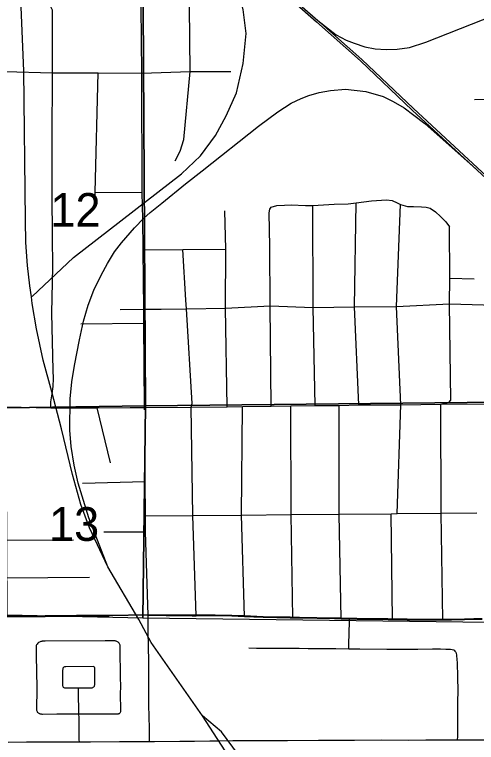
# Model space of a CAD drawing. Extents: x 0 to 40.2, y 0 to 22.
# Drawn here: x 2.971 to 3.545, y 17.261 to 18.165 of the extents above; entities that cross this region are included whole.
import ezdxf

# ---------------------------------------------------------------- set-up
doc = ezdxf.new("R2010")
doc.units = 0
for name, color, linetype in [('GM_X_City_Street', 7, 'Continuous'), ('GM_X_Corporation', 7, 'Continuous'), ('GM_X_Major_Lake_Text', 7, 'Continuous'), ('GM_X_Major_River', 7, 'Continuous'), ('GM_X_Unincorporated_Location', 7, 'Continuous')]:
    doc.layers.add(name, color=color, linetype=linetype)

msp = doc.modelspace()

# ---------------------------------------------------------------- linework, layer by layer
at = {"layer": 'GM_X_Corporation'}
for points in [[(4.11898, 18.68419), (4.13231, 17.68919), (3.13419, 17.6788), (3.1284, 18.66934)], [(3.1284, 18.66934), (3.13419, 17.6788), (2.96095, 17.67632), (2.96072, 17.91012), (2.96123, 18.66685)], [(4.13231, 17.68919), (4.13209, 17.4086), (3.75982, 17.40742), (3.1308, 17.4152), (3.13419, 17.6788)], [(2.96095, 17.67632), (3.13419, 17.6788), (3.1308, 17.4152), (2.96215, 17.41928)]]:
    msp.add_lwpolyline(points, close=True, dxfattribs=at)
for points in [[(2.9617, 17.41769), (2.99033, 17.41796), (3.00943, 17.4181), (3.03209, 17.41845), (3.04821, 17.41854), (3.08872, 17.4187), (3.13707, 17.41967), (3.1596, 17.41929), (3.19192, 17.41893), (3.19659, 17.41895), (3.22053, 17.41908), (3.24107, 17.41867), (3.25657, 17.41809), (3.27994, 17.41721), (3.31354, 17.41646), (3.31679, 17.41639), (3.32524, 17.41618), (3.36862, 17.41544), (3.37667, 17.41527), (3.38417, 17.41511), (3.38703, 17.41504), (3.39658, 17.41478), (3.41211, 17.41473), (3.43513, 17.41443), (3.44068, 17.41434), (3.45874, 17.41404), (3.49872, 17.41383), (3.50305, 17.41386), (3.51367, 17.41392), (3.52995, 17.41417), (3.5416, 17.41451), (3.55201, 17.41452)], [(3.55201, 17.41452), (3.5416, 17.41451), (3.52995, 17.41417), (3.51367, 17.41392), (3.50305, 17.41386), (3.49872, 17.41383), (3.45874, 17.41404), (3.44068, 17.41434), (3.43513, 17.41443), (3.41211, 17.41473), (3.39658, 17.41478), (3.38703, 17.41504), (3.38417, 17.41511), (3.37667, 17.41527), (3.36862, 17.41544), (3.32524, 17.41618), (3.31679, 17.41639), (3.31354, 17.41646), (3.27994, 17.41721), (3.25657, 17.41809), (3.24107, 17.41867), (3.22053, 17.41908), (3.19659, 17.41895), (3.19192, 17.41893), (3.1596, 17.41929), (3.13707, 17.41967), (3.08872, 17.4187), (3.04821, 17.41854), (3.03209, 17.41845), (3.00943, 17.4181), (2.99033, 17.41796), (2.9617, 17.41769)], [(3.55201, 17.41452), (3.5416, 17.41451), (3.52995, 17.41417), (3.51367, 17.41392), (3.50305, 17.41386), (3.49872, 17.41383), (3.45874, 17.41404), (3.44068, 17.41434), (3.43513, 17.41443), (3.41211, 17.41473), (3.39658, 17.41478), (3.38703, 17.41504), (3.38417, 17.41511), (3.37667, 17.41527), (3.36862, 17.41544), (3.32524, 17.41618), (3.31679, 17.41639), (3.31354, 17.41646), (3.27994, 17.41721), (3.25657, 17.41809), (3.24107, 17.41867), (3.22053, 17.41908), (3.19659, 17.41895), (3.19192, 17.41893), (3.1596, 17.41929), (3.13707, 17.41967), (3.08872, 17.4187), (3.04821, 17.41854), (3.03209, 17.41845), (3.00943, 17.4181), (2.99033, 17.41796), (2.9617, 17.41769)], [(2.9617, 17.41769), (2.99033, 17.41796), (3.00943, 17.4181), (3.03209, 17.41845), (3.04821, 17.41854), (3.08872, 17.4187), (3.13707, 17.41967), (3.1596, 17.41929), (3.19192, 17.41893), (3.19659, 17.41895), (3.22053, 17.41908), (3.24107, 17.41867), (3.25657, 17.41809), (3.27994, 17.41721), (3.31354, 17.41646), (3.31679, 17.41639), (3.32524, 17.41618), (3.36862, 17.41544), (3.37667, 17.41527), (3.38417, 17.41511), (3.38703, 17.41504), (3.39658, 17.41478), (3.41211, 17.41473), (3.43513, 17.41443), (3.44068, 17.41434), (3.45874, 17.41404), (3.49872, 17.41383), (3.50305, 17.41386), (3.51367, 17.41392), (3.52995, 17.41417), (3.5416, 17.41451), (3.55201, 17.41452)], [(3.55201, 17.41452), (3.5416, 17.41451), (3.52995, 17.41417), (3.51367, 17.41392), (3.50305, 17.41386), (3.49872, 17.41383), (3.45874, 17.41404), (3.44068, 17.41434), (3.43513, 17.41443), (3.41211, 17.41473), (3.39658, 17.41478), (3.38703, 17.41504), (3.38417, 17.41511), (3.37667, 17.41527), (3.36862, 17.41544), (3.32524, 17.41618), (3.31679, 17.41639), (3.31354, 17.41646), (3.27994, 17.41721), (3.25657, 17.41809), (3.24107, 17.41867), (3.22053, 17.41908), (3.19659, 17.41895), (3.19192, 17.41893), (3.1596, 17.41929), (3.13707, 17.41967), (3.08872, 17.4187), (3.04821, 17.41854), (3.03209, 17.41845), (3.00943, 17.4181), (2.99033, 17.41796), (2.9617, 17.41769)], [(2.9617, 17.41769), (2.99033, 17.41796), (3.00943, 17.4181), (3.03209, 17.41845), (3.04821, 17.41854), (3.08872, 17.4187), (3.13707, 17.41967), (3.1596, 17.41929), (3.19192, 17.41893), (3.19659, 17.41895), (3.22053, 17.41908), (3.24107, 17.41867), (3.25657, 17.41809), (3.27994, 17.41721), (3.31354, 17.41646), (3.31679, 17.41639), (3.32524, 17.41618), (3.36862, 17.41544), (3.37667, 17.41527), (3.38417, 17.41511), (3.38703, 17.41504), (3.39658, 17.41478), (3.41211, 17.41473), (3.43513, 17.41443), (3.44068, 17.41434), (3.45874, 17.41404), (3.49872, 17.41383), (3.50305, 17.41386), (3.51367, 17.41392), (3.52995, 17.41417), (3.5416, 17.41451), (3.55201, 17.41452)]]:
    msp.add_lwpolyline(points, dxfattribs=at)
at = {"layer": 'GM_X_Major_Lake_Text'}
for points in [[(2.93726, 17.69353), (2.93877, 17.6924), (2.96139, 17.67783), (3.0163, 17.67668), (3.06737, 17.67662)], [(3.11488, 17.67671), (3.13289, 17.67675), (3.13423, 17.67676), (3.19078, 17.67743), (3.23544, 17.6778), (3.25468, 17.67824), (3.29027, 17.67869), (3.31457, 17.67895), (3.34467, 17.67951), (3.37432, 17.67943), (3.39891, 17.68003), (3.45093, 17.6804), (3.50079, 17.68099), (3.55771, 17.68159), (3.57339, 17.68181), (3.63343, 17.68293)], [(3.06737, 17.67662), (3.07411, 17.67661), (3.11488, 17.67671)]]:
    msp.add_lwpolyline(points, dxfattribs=at)
at = {"layer": 'GM_X_Major_River'}
for points in [[(3.17893, 17.96677), (3.20214, 17.98942), (3.22086, 18.01438), (3.23408, 18.03898), (3.24692, 18.06733), (3.25513, 18.1039), (3.25885, 18.14122), (3.25513, 18.17108), (3.24543, 18.21063), (3.23335, 18.23466), (3.21707, 18.25616), (3.16603, 18.30644)], [(3.30443, 18.1928), (3.34645, 18.1555)], [(3.30596, 18.19455), (3.348, 18.15723)], [(3.348, 18.15723), (3.37096, 18.13968), (3.38311, 18.13303), (3.39324, 18.12898), (3.40623, 18.12466), (3.41916, 18.12213), (3.43274, 18.12138), (3.4465, 18.12166), (3.46177, 18.12382), (3.48191, 18.13019), (3.55262, 18.15791), (3.62812, 18.18751)], [(3.12587, 17.41372), (3.08729, 17.47893), (3.06471, 17.52756), (3.05386, 17.55651), (3.04358, 17.5937), (3.02969, 17.6503), (3.01767, 17.69647), (3.00711, 17.73555), (2.99857, 17.77463), (2.9935, 17.80604), (2.99234, 17.81429), (2.9905, 17.82787), (2.98769, 17.8533), (2.98529, 17.88154), (2.9849, 17.90952), (2.98289, 18.09501), (2.97948, 18.17371)], [(3.34645, 18.1555), (3.40098, 18.10707), (3.46511, 18.04617), (3.57841, 17.94139), (3.82062, 17.71495), (4.1455, 17.41498)], [(3.348, 18.15723), (3.40256, 18.10878), (3.46671, 18.04785), (3.58, 17.94309), (3.8222, 17.71665), (4.14708, 17.41668)], [(3.08729, 17.47893), (3.06356, 17.54001), (3.05024, 17.58314), (3.04561, 17.60543), (3.04185, 17.62844), (3.03996, 17.64885), (3.0404, 17.68778), (3.04242, 17.70863), (3.0459, 17.72904), (3.05212, 17.76088), (3.05704, 17.78404), (3.06269, 17.80387), (3.06992, 17.82254), (3.0789, 17.84121), (3.087, 17.85568), (3.0954, 17.87001), (3.10423, 17.88145), (3.12058, 17.90012), (3.13202, 17.91199), (3.13983, 17.91893), (3.15416, 17.93066), (3.18383, 17.95434), (3.20459, 17.97082), (3.27418, 18.02607), (3.29833, 18.04391), (3.31483, 18.05447), (3.32729, 18.06056), (3.33667, 18.06431), (3.34984, 18.06807), (3.36373, 18.07053), (3.38223, 18.07185), (3.40756, 18.06908), (3.42897, 18.06301), (3.44171, 18.05679), (3.45516, 18.04883), (3.46717, 18.03971), (3.48077, 18.02959), (3.54471, 17.97255)], [(2.99348, 17.81465), (3.0448, 17.86313), (3.17893, 17.96677)], [(3.42749, 16.31236), (3.42143, 16.37549), (3.41839, 16.40637), (3.36203, 16.74823), (3.34427, 16.83879), (3.33799, 16.8832), (3.32359, 16.97894), (3.3149, 17.0308), (3.29684, 17.09734), (3.28734, 17.13347), (3.26263, 17.1924), (3.24648, 17.22948), (3.20467, 17.29412), (3.141, 17.38537), (3.12587, 17.41372)], [(4.03805, 16.15637), (3.69141, 16.63399), (3.24242, 17.25514), (3.22847, 17.27443), (3.20468, 17.29411), (3.20467, 17.29412)]]:
    msp.add_lwpolyline(points, dxfattribs=at)
at = {"layer": 'GM_X_Unincorporated_Location'}
for p, q in [((3.07153, 17.9444), (3.12994, 17.94375)), ((3.51193, 17.83734), (3.54196, 17.83652)), ((3.05394, 17.7808), (3.13206, 17.78143)), ((3.09065, 17.6084), (3.07411, 17.67661)), ((3.056, 17.58297), (3.13363, 17.58521)), ((3.44091, 17.41378), (3.43914, 17.54509)), ((3.08249, 17.52239), (3.13413, 17.52261))]:
    msp.add_line(p, q, dxfattribs=at)
for points in [[(3.0163, 17.67668), (3.0163, 17.68397), (3.01823, 17.694), (3.01935, 17.70277), (3.01972, 17.7128), (3.01952, 17.72337), (3.01779, 17.79387), (3.01898, 17.8516), (3.01846, 17.88868), (3.01823, 17.94129), (3.01831, 18.00772), (3.01844, 18.09243), (3.01875, 18.16994), (3.01645, 18.17417), (3.01593, 18.31105), (3.0172, 18.31238), (3.01677, 18.34166)], [(3.12934, 18.0902), (3.12933, 18.09209), (3.1287, 18.17477)], [(3.17097, 17.98292), (3.17727, 17.99497), (3.18172, 18.00971), (3.18971, 18.0938), (3.18866, 18.17481)], [(2.88565, 18.09458), (2.93786, 18.09431), (2.95954, 18.09404), (3.01844, 18.09243), (3.0752, 18.09243), (3.12933, 18.09209), (3.18971, 18.0938), (3.23282, 18.0938), (3.23997, 18.0938)], [(3.07157, 17.92655), (3.07153, 17.9444), (3.0752, 18.09243)], [(3.13729, 17.41912), (3.13413, 17.52261), (3.13397, 17.54235), (3.13363, 17.58521), (3.13423, 17.67676), (3.13291, 17.67416), (3.13289, 17.67675), (3.13206, 17.78143), (3.13191, 17.79887), (3.13132, 17.87277), (3.13058, 17.91067), (3.12994, 17.94375), (3.12934, 18.0902)], [(3.54263, 18.05902), (3.62867, 18.06068), (3.75346, 18.06164), (3.79723, 18.0611), (3.83901, 18.05996), (3.87868, 18.05848), (4.00662, 18.06016), (4.06623, 18.06085), (4.12108, 18.06125)], [(3.28994, 17.92565), (3.29711, 17.92751), (3.30681, 17.92807), (3.31476, 17.92833), (3.33274, 17.92755), (3.34177, 17.92747), (3.36811, 17.92922), (3.3858, 17.92985), (3.39572, 17.93085), (3.41478, 17.93334), (3.43321, 17.93464), (3.44049, 17.93368), (3.44658, 17.93111), (3.45059, 17.929), (3.45947, 17.92643), (3.46698, 17.92636), (3.47687, 17.9261), (3.48236, 17.92561), (3.48734, 17.92413), (3.49425, 17.91967), (3.50049, 17.91387), (3.50696, 17.90733), (3.51164, 17.90132)], [(3.34467, 17.67951), (3.34202, 17.80123), (3.34177, 17.92747)], [(3.39891, 17.68003), (3.39339, 17.80181), (3.39572, 17.93085)], [(3.44631, 17.54516), (3.45093, 17.6804), (3.44551, 17.8024), (3.45059, 17.929)], [(3.23544, 17.6778), (3.23334, 17.80001), (3.23376, 17.87354), (3.23235, 17.92097)], [(3.29027, 17.67869), (3.2889, 17.8029), (3.28845, 17.87683), (3.28764, 17.91855), (3.28823, 17.92327), (3.28994, 17.92565)], [(3.50328, 17.4133), (3.50108, 17.54565), (3.50079, 17.68099), (3.51052, 17.68293), (3.51327, 17.6859), (3.51134, 17.80538), (3.51193, 17.83734), (3.51164, 17.90132)], [(3.13132, 17.87277), (3.18052, 17.87314), (3.23376, 17.87354)], [(3.19681, 17.4184), (3.19284, 17.54288), (3.19078, 17.67743), (3.19192, 17.68207), (3.18495, 17.79947), (3.18433, 17.80996), (3.18052, 17.87314)], [(3.1024, 17.79854), (3.13191, 17.79887), (3.15357, 17.79912), (3.18495, 17.79947), (3.23334, 17.80001), (3.2889, 17.8029), (3.34202, 17.80123), (3.39339, 17.80181), (3.44551, 17.8024), (3.51134, 17.80538), (3.56769, 17.80377), (3.57315, 17.80383), (3.63208, 17.80603)], [(3.2568, 17.41753), (3.25317, 17.54343), (3.25468, 17.67824)], [(3.31702, 17.41583), (3.31489, 17.54398), (3.31457, 17.67895)], [(3.37689, 17.41472), (3.3747, 17.54452), (3.3747, 17.54558), (3.37432, 17.67943)], [(3.13397, 17.54235), (3.19284, 17.54288), (3.25317, 17.54343), (3.31489, 17.54398), (3.3747, 17.54452), (3.43914, 17.54509), (3.44631, 17.54516), (3.50108, 17.54565), (3.54563, 17.54605)], [(2.78714, 17.51159), (2.96097, 17.51238), (3.04468, 17.51276)], [(2.79062, 17.4645), (2.95696, 17.46548), (2.96094, 17.46551), (3.0646, 17.46612)], [(2.96193, 17.41713), (2.99056, 17.4174), (3.00965, 17.41754), (3.03231, 17.41789), (3.04843, 17.41798), (3.08895, 17.41814)], [(3.13729, 17.41912), (3.15983, 17.41874), (3.19214, 17.41837), (3.19681, 17.4184), (3.22076, 17.41853), (3.2413, 17.41812), (3.2568, 17.41753), (3.28017, 17.41665), (3.31377, 17.4159), (3.31702, 17.41583), (3.32546, 17.41562), (3.36885, 17.41489), (3.37689, 17.41472), (3.38439, 17.41456), (3.38726, 17.41448), (3.39681, 17.41423), (3.41234, 17.41417), (3.43535, 17.41387), (3.44091, 17.41378), (3.45896, 17.41348), (3.49895, 17.41328), (3.50328, 17.4133), (3.5139, 17.41336), (3.53018, 17.41362), (3.54182, 17.41395), (3.55223, 17.41396)], [(3.13914, 17.26244), (3.1391, 17.26556), (3.13893, 17.27917), (3.13854, 17.29249), (3.13834, 17.30803), (3.13809, 17.33607), (3.13808, 17.35455), (3.13803, 17.36142), (3.13742, 17.39926), (3.13744, 17.41308), (3.13729, 17.41912)], [(3.38646, 17.37753), (3.38658, 17.38312), (3.38718, 17.41075), (3.38726, 17.41448)], [(3.05145, 17.29651), (3.06349, 17.2966), (3.0665, 17.29663), (3.07503, 17.2965), (3.08671, 17.29647), (3.09471, 17.29657), (3.09955, 17.29674), (3.10039, 17.29681), (3.10104, 17.29698), (3.10165, 17.29723), (3.10224, 17.29761), (3.10274, 17.29813), (3.1031, 17.29871), (3.10329, 17.29938), (3.10335, 17.30006), (3.10342, 17.30106), (3.10342, 17.30279), (3.10321, 17.32041), (3.10329, 17.33172), (3.10316, 17.34093), (3.10273, 17.37902), (3.10268, 17.38037), (3.10263, 17.38116), (3.10257, 17.38179), (3.10235, 17.38272), (3.10194, 17.38351), (3.10136, 17.38421), (3.10076, 17.3849), (3.10005, 17.38545), (3.09933, 17.38595), (3.09843, 17.38641), (3.09782, 17.38667), (3.09716, 17.38689), (3.09646, 17.38711), (3.09558, 17.38727), (3.09459, 17.38733), (3.0928, 17.38732), (3.08414, 17.38717), (3.00944, 17.38671), (3.00689, 17.38674), (3.00588, 17.38666), (3.00526, 17.3866), (3.00422, 17.38641), (3.00333, 17.38615), (3.0024, 17.3858), (3.00134, 17.38513), (3.00072, 17.38469), (3.00019, 17.38422), (2.99935, 17.38331), (2.99877, 17.38235), (2.99844, 17.38136), (2.99832, 17.38068), (2.99829, 17.37983), (2.99827, 17.37763), (2.99821, 17.37426), (2.99829, 17.36297), (2.99863, 17.3549), (2.9988, 17.34866), (2.9989, 17.34187), (2.99895, 17.33623), (2.99893, 17.32696), (2.99878, 17.30318), (2.9988, 17.30252), (2.9989, 17.3014), (2.99904, 17.3005), (2.99934, 17.29952), (2.99971, 17.29886), (3.00023, 17.29825), (3.00085, 17.29778), (3.00148, 17.2974), (3.00231, 17.29704), (3.00297, 17.29683), (3.00367, 17.29666), (3.00439, 17.29652), (3.00514, 17.29643), (3.00601, 17.29634), (3.02382, 17.29649), (3.04725, 17.29651), (3.05145, 17.29651)], [(3.26216, 17.37847), (3.27196, 17.37817), (3.28458, 17.37828), (3.31436, 17.37819), (3.32466, 17.37799), (3.33587, 17.3778), (3.37036, 17.37768), (3.38646, 17.37753)], [(3.38646, 17.37753), (3.40018, 17.3774), (3.43375, 17.37698), (3.47218, 17.37694), (3.49032, 17.37721), (3.50045, 17.37716), (3.50711, 17.37706), (3.51268, 17.37675), (3.51493, 17.37644), (3.51635, 17.37612), (3.51737, 17.37554), (3.51829, 17.37453), (3.51921, 17.37302), (3.51972, 17.37151), (3.52005, 17.36992), (3.52031, 17.36815), (3.52073, 17.36471), (3.52101, 17.35898), (3.52149, 17.3436), (3.52174, 17.32412), (3.52157, 17.31268), (3.52141, 17.28015), (3.52123, 17.26853), (3.52117, 17.26435)], [(3.05094, 17.32884), (3.05798, 17.32879), (3.06638, 17.32894), (3.06766, 17.32904), (3.06848, 17.32927), (3.06907, 17.32961), (3.06983, 17.33022), (3.07053, 17.33112), (3.07086, 17.33199), (3.07102, 17.33269), (3.07111, 17.33368), (3.07117, 17.33483), (3.07124, 17.33974), (3.07122, 17.34659), (3.07122, 17.35267), (3.07104, 17.35369), (3.07061, 17.35448), (3.06996, 17.35505), (3.06908, 17.35543), (3.03507, 17.35518), (3.03396, 17.35519), (3.03334, 17.35507), (3.03258, 17.35466), (3.03206, 17.35419), (3.03157, 17.35353), (3.03131, 17.35286), (3.03108, 17.34998), (3.03107, 17.3369), (3.03108, 17.33526), (3.03106, 17.33411), (3.0311, 17.33179), (3.03121, 17.33116), (3.0315, 17.33055), (3.03199, 17.32984), (3.03266, 17.32931), (3.03364, 17.32909), (3.05094, 17.32884)], [(3.05145, 17.29651), (3.05098, 17.32449), (3.05094, 17.32884)], [(3.05191, 17.26174), (3.05188, 17.26442), (3.05153, 17.29154), (3.05145, 17.29651)], [(2.96344, 17.26136), (2.9861, 17.26172), (3.05191, 17.26174), (3.06581, 17.26174), (3.10159, 17.26229), (3.13914, 17.26244), (3.14506, 17.26245), (3.17678, 17.26265), (3.1948, 17.26286), (3.21406, 17.26316), (3.22649, 17.26329), (3.24265, 17.26347), (3.26191, 17.26368), (3.3104, 17.2637), (3.34894, 17.26391), (3.39369, 17.26399), (3.42726, 17.26435), (3.4602, 17.26413), (3.48196, 17.26421), (3.52117, 17.26435), (3.57457, 17.26451)]]:
    msp.add_lwpolyline(points, dxfattribs=at)

# ---------------------------------------------------------------- texts
at = {"layer": 'GM_X_City_Street'}
for s, p in [('12', (3.01593, 17.90122)), ('13', (3.01426, 17.51133))]:
    msp.add_text(s, height=0.041856, rotation=0.00001, dxfattribs=at).set_placement(p)

doc.saveas('drawing.dxf')
